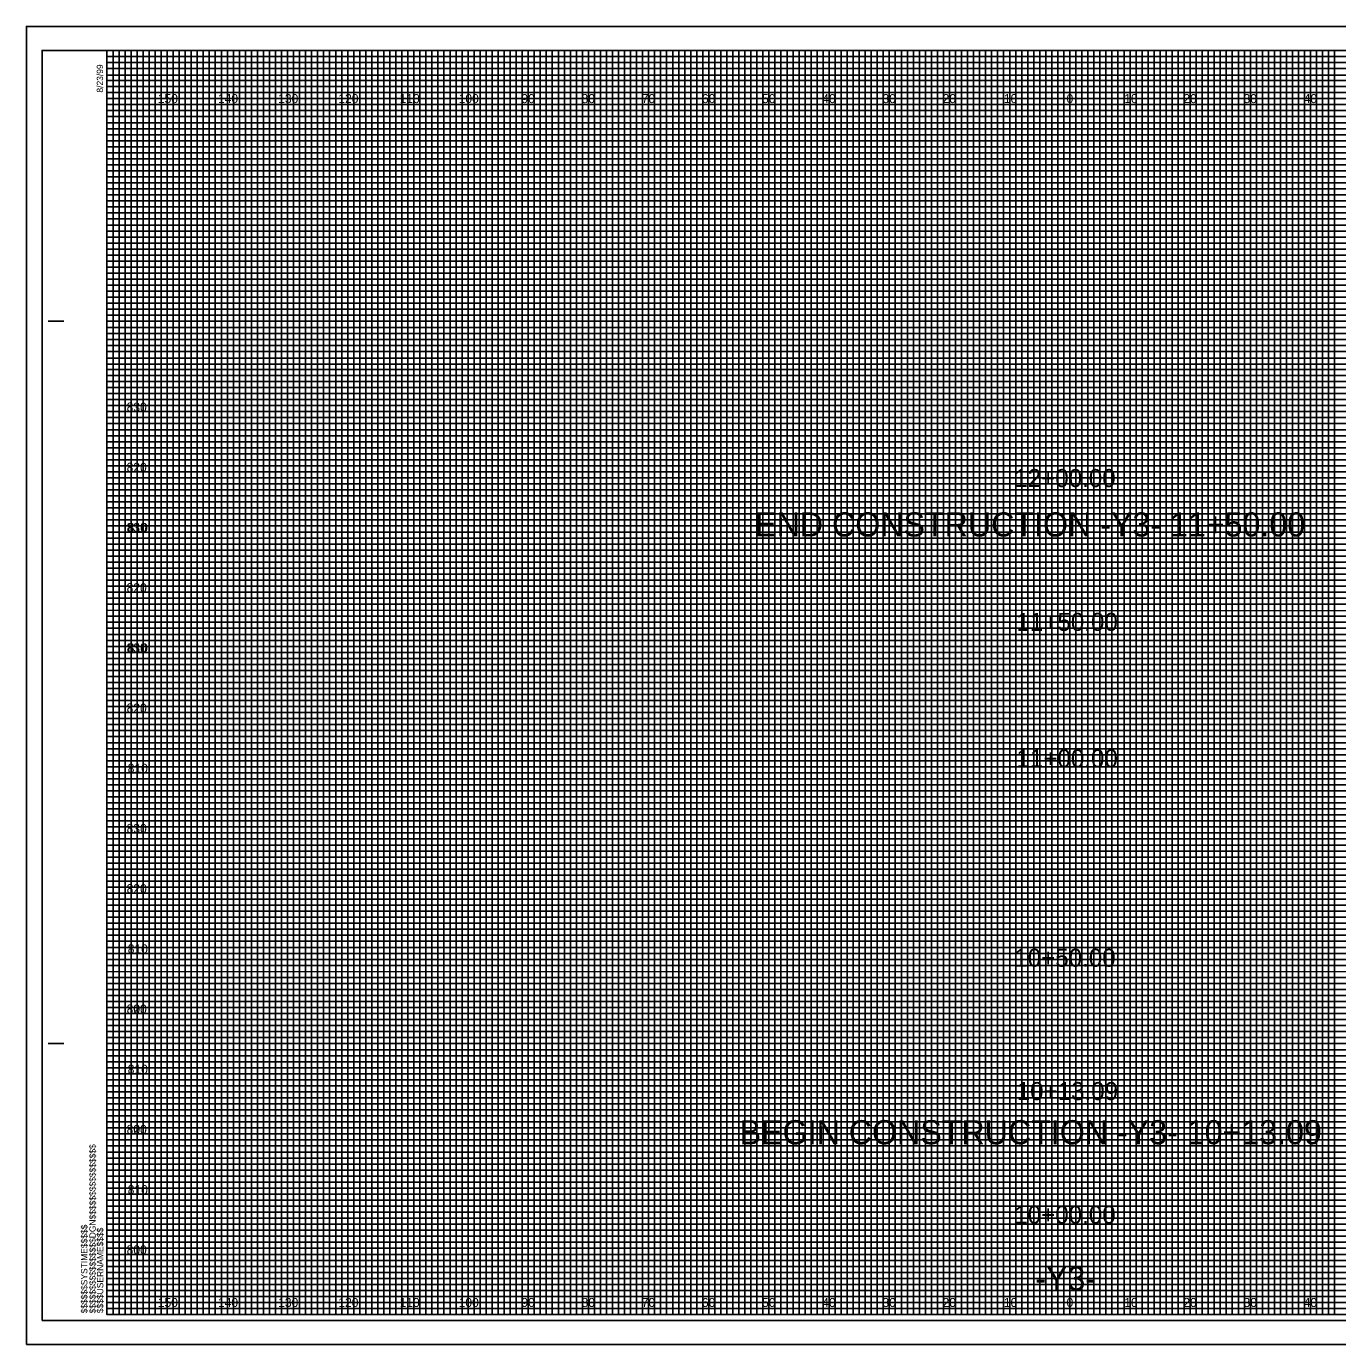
# Model space of a CAD drawing. Extents: x -13 to 323, y -5 to 214.
# Drawn here: x -13.4 to 204.5, y -5 to 214 of the extents above; entities that cross this region are included whole.
import ezdxf

# ---------------------------------------------------------------- set-up
doc = ezdxf.new("R2010")
doc.units = 0
for name, color, linetype in [('Prop XS Alignment Label', 7, 'Continuous'), ('Prop XS Elevation Labels', 7, 'Continuous'), ('Prop XS Offset Labels', 7, 'Continuous'), ('Prop XS Station Labels', 7, 'Continuous'), ('Sheet Cross Section CELL', 7, 'Continuous'), ('Sheet Cross Section Grid Major CELL', 7, 'Continuous'), ('Sheet Cross Section Grid Middle CELL', 7, 'Continuous'), ('Sheet Cross Section Grid Minor 1 CELL', 7, 'Continuous'), ('Sheet Cross Section Grid Minor 2 CELL', 7, 'Continuous'), ('Sheet Cutting Line CELL', 7, 'Continuous'), ('Sheet DOT Grid CELL', 7, 'Continuous'), ('Sheet Plot Border Inside CELL', 7, 'Continuous'), ('Sheet Plot Border Outside CELL', 7, 'Continuous')]:
    doc.layers.add(name, color=color, linetype=linetype)

msp = doc.modelspace()

# ---------------------------------------------------------------- linework, layer by layer
at = {"layer": 'Sheet Cross Section CELL'}
for p, q in [((-9.8, 165), (-7.3, 165)), ((-9.7, 165), (-7.2, 165)), ((-9.8, 45), (-7.3, 45)), ((-9.7, 45), (-7.2, 45)), ((0, 0), (0, 0)), ((0, 0), (0, 0)), ((0, 0), (0, 0)), ((0, 0), (0, 0)), ((0, 0), (0, 0)), ((0, 0), (0, 0)), ((0, 0), (0, 0))]:
    msp.add_line(p, q, dxfattribs=at)
msp.add_lwpolyline([(320, 210), (0, 210), (0, 0), (320, 0)], close=True, dxfattribs=at)
at = {"layer": 'Sheet Cross Section Grid Major CELL'}
for p, q in [((10, 210), (0, 210)), ((10, 0), (10, 210)), ((30, 210), (20, 210)), ((20, 210), (20, 0)), ((30, 0), (30, 210)), ((50, 210), (40, 210)), ((40, 210), (40, 0)), ((50, 0), (50, 210)), ((70, 210), (60, 210)), ((60, 210), (60, 0)), ((70, 0), (70, 210)), ((90, 210), (80, 210)), ((80, 210), (80, 0)), ((90, 0), (90, 210)), ((110, 210), (100, 210)), ((100, 210), (100, 0)), ((110, 0), (110, 210)), ((130, 210), (120, 210)), ((120, 210), (120, 0)), ((130, 0), (130, 210)), ((150, 210), (140, 210)), ((140, 210), (140, 0)), ((150, 0), (150, 210)), ((170, 210), (160, 210)), ((160, 210), (160, 0)), ((170, 0), (170, 210)), ((190, 210), (180, 210)), ((180, 210), (180, 0)), ((190, 0), (190, 210)), ((210, 210), (200, 210)), ((200, 210), (200, 0)), ((20, 0), (10, 0)), ((40, 0), (30, 0)), ((60, 0), (50, 0)), ((80, 0), (70, 0)), ((100, 0), (90, 0)), ((120, 0), (110, 0)), ((140, 0), (130, 0)), ((160, 0), (150, 0)), ((180, 0), (170, 0)), ((200, 0), (190, 0))]:
    msp.add_line(p, q, dxfattribs=at)
for points in [[(0, 200), (320, 200), (320, 190), (0, 190)], [(0, 180), (320, 180), (320, 170), (0, 170)], [(0, 160), (320, 160), (320, 150), (0, 150)], [(0, 140), (320, 140), (320, 130), (0, 130)], [(0, 120), (320, 120), (320, 110), (0, 110)], [(0, 100), (320, 100), (320, 90), (0, 90)], [(0, 80), (320, 80), (320, 70), (0, 70)], [(0, 60), (320, 60), (320, 50), (0, 50)], [(0, 40), (320, 40), (320, 30), (0, 30)], [(0, 20), (320, 20), (320, 10), (0, 10)]]:
    msp.add_lwpolyline(points, dxfattribs=at)
at = {"layer": 'Sheet Cross Section Grid Middle CELL'}
for points in [[(0, 210), (5, 210), (5, 0), (15, 0), (15, 210), (25, 210), (25, 0), (35, 0), (35, 210), (45, 210), (45, 0), (55, 0), (55, 210), (65, 210), (65, 0), (75, 0), (75, 210), (85, 210), (85, 0), (95, 0), (95, 210), (105, 210), (105, 0), (115, 0), (115, 210), (125, 210), (125, 0), (135, 0), (135, 210), (145, 210), (145, 0), (155, 0), (155, 210), (165, 210), (165, 0), (175, 0), (175, 210), (185, 210), (185, 0), (195, 0), (195, 210), (205, 210)], [(0, 205), (275, 205)], [(0, 185), (320, 185), (320, 195), (0, 195)], [(0, 165), (320, 165), (320, 175), (0, 175)], [(0, 145), (320, 145), (320, 155), (0, 155)], [(0, 125), (320, 125), (320, 135), (0, 135)], [(0, 105), (320, 105), (320, 115), (0, 115)], [(0, 85), (320, 85), (320, 95), (0, 95)], [(0, 65), (320, 65), (320, 75), (0, 75)], [(0, 45), (320, 45), (320, 55), (0, 55)], [(0, 25), (320, 25), (320, 35), (0, 35)], [(0, 5), (320, 5), (320, 15), (0, 15)]]:
    msp.add_lwpolyline(points, dxfattribs=at)
at = {"layer": 'Sheet Cross Section Grid Minor 1 CELL'}
for p, q in [((0, 209), (260, 209)), ((260, 207.98), (0, 207.98)), ((0, 207.98), (0, 207)), ((0, 207), (260, 207)), ((260, 205.89), (0, 205.89)), ((0, 205.89), (0, 204)), ((0, 204), (320, 204))]:
    msp.add_line(p, q, dxfattribs=at)
for points in [[(0, 203), (270, 203), (320, 203), (320, 202), (0, 202)], [(0, 201), (320, 201), (320, 199), (0, 199)], [(0, 198), (320, 198), (320, 197), (0, 196.98)], [(0, 196), (320, 196), (320, 194), (0, 194)], [(0, 193), (320, 193), (320, 192), (0, 192)], [(0, 191), (320, 191), (320, 189), (0, 189)], [(0, 188), (320, 188), (320, 187), (0, 187)], [(0, 186), (320, 186), (320, 184), (0, 184)], [(0, 183), (320, 183), (320, 182), (0, 182)], [(0, 181), (320, 181), (320, 179), (0, 179)], [(0, 178), (320, 178), (320, 177), (0, 177)], [(0, 176), (320, 176), (320, 173.95), (320, 173), (320, 172), (0, 172)], [(0, 174), (320, 174), (320, 173), (0, 173)], [(0, 171), (320, 171), (320, 169), (0, 169.03)], [(0, 169.03), (320, 169), (320, 168), (0, 168)], [(0, 167), (320, 167), (320, 166), (0, 166)], [(0, 164), (320, 164), (320, 163), (0, 163)], [(0, 162), (320, 162), (320, 161), (0, 161)], [(-0.07, 158.89), (320, 158.89), (320, 157.88), (-0.07, 157.88)], [(0, 157), (320, 157), (320, 156), (0, 156)], [(0, 154), (320, 154), (320, 153), (0, 153)], [(0, 152), (320, 152), (320, 151), (0, 151)], [(0, 149), (320, 149), (320, 148), (0, 148)], [(0, 147), (320, 147), (320, 146), (0, 146)], [(0, 144), (320, 144), (320, 143), (0, 143)], [(0, 142), (320, 142), (320, 141), (0, 141)], [(0, 139), (320, 139), (319.99, 137.98), (0, 138)], [(0, 137), (320, 137), (320, 136), (0, 136)], [(0, 134), (320, 134), (320, 133), (0, 133)], [(0, 132), (320, 132), (320, 131), (0, 131)], [(0, 129), (320, 129), (320, 128), (0, 128)], [(0, 127), (320, 127), (320, 126), (0, 126)], [(0, 124), (320, 124), (320, 123), (0, 123)], [(0, 122), (320, 122), (320, 121), (0, 121)], [(0, 119), (320, 119), (320, 118), (0, 118)], [(0, 116.99), (320.07, 116.91), (320, 116), (0, 116)], [(0, 114), (320, 114), (320, 113), (0, 113)], [(0, 112), (320, 112), (320, 111), (0, 111)], [(0, 109), (320, 109), (320, 108), (0, 108)], [(0, 107), (320, 107), (320, 106), (0, 106)], [(0, 104), (320, 104), (320, 103), (0, 103)], [(0, 102), (320, 102), (320, 101), (0, 101)], [(0, 99), (320, 99), (320, 98), (0, 98)], [(0, 97), (320, 97), (320, 96), (0, 96)], [(0, 94), (320, 94), (320, 93), (0, 93)], [(0, 92), (320, 92), (320, 91), (0, 91)], [(0, 89), (320, 89), (320, 88), (0, 88)], [(0, 87), (320, 87), (320, 86), (0, 86)], [(0, 84), (320, 84), (320, 83), (0, 83)], [(0, 82), (320, 82), (320, 81), (0, 81)], [(0, 79), (320, 79), (319.99, 77.98), (0, 78)], [(0, 77), (320, 77), (320, 76), (0, 76)], [(0, 74), (320, 74), (320, 73), (0, 73)], [(0, 72), (320, 72), (320, 71), (0, 71)], [(0, 69), (320, 69), (320, 68), (0, 68)], [(0, 67), (320, 67), (320, 66), (0, 66)], [(0, 64), (320, 64), (320, 63), (0, 63)], [(0, 62), (320, 62), (320, 61), (0, 61)], [(0, 59), (320, 59), (320, 58), (0, 58)], [(0, 56.99), (320.07, 56.91), (320, 56), (0, 56)], [(0, 54), (320, 54), (320, 53), (0, 53)], [(0, 52), (320, 52), (320, 51), (0, 51)], [(0, 49), (320, 49), (320, 48), (0, 48)], [(0, 47), (320, 47), (320, 46), (0, 46)], [(0, 44), (320, 44), (320, 43), (0, 43)], [(0, 42), (320, 42), (320, 41), (0, 41)], [(0, 39), (320, 39), (320, 38), (0, 38)], [(0, 37), (320, 37), (320, 36), (0, 36)], [(0, 34), (320, 34), (320, 33), (0, 33)], [(0, 32), (320, 32), (320, 31), (0, 31)], [(0, 29), (320, 29), (320, 28), (0, 28)], [(0, 27), (320, 27), (320, 26), (0, 26)], [(0, 24), (320, 24), (320, 23), (0, 23)], [(0, 22), (320, 22), (320, 21), (0, 21)], [(0, 19), (320, 19), (320, 18), (0, 18)], [(0, 17), (320, 17), (320, 16), (0, 16)], [(0, 14), (320, 14), (320, 13), (0, 13)], [(0, 12), (320, 12), (320, 11), (0, 11)], [(0, 9), (320, 9), (320, 8), (0, 8)], [(0, 7), (320, 7), (320, 6), (0, 6)], [(0, 4), (320, 4), (320, 3), (0, 3)], [(0, 2), (320, 2), (320, 1), (0, 1)]]:
    msp.add_lwpolyline(points, dxfattribs=at)
at = {"layer": 'Sheet Cross Section Grid Minor 2 CELL'}
for points in [[(0, 0), (1, 0), (1, 210), (2, 210), (2, 0)], [(2, 0), (3, 0), (3, 210), (4, 210), (4, 0)], [(5, 0), (6, 0), (6, 210), (7, 210), (7, 0)], [(7, 0), (8, 0), (8, 210), (9, 210), (9, 0)], [(10, 0), (11, 0), (11, 210), (12, 210), (12, 0)], [(12, 0), (13, 0), (13, 210), (14, 210), (14, 0)], [(15, 0), (16, 0), (16, 210), (17, 210), (17, 0)], [(17, 0), (18, 0), (18, 210), (19, 210), (19, 0)], [(20, 0), (21, 0), (21, 210), (22, 210), (22, 0)], [(22, 0), (23, 0), (23, 210), (24, 210), (24, 0)], [(25, 0), (26, 0), (26, 210), (27, 210), (27, 0)], [(27, 0), (28, 0), (28, 210), (29, 210), (29, 0)], [(30, 0), (31, 0), (31, 210), (32, 210), (32, 0)], [(32, 0), (33, 0), (33, 210), (34, 210), (34, 0)], [(35, 0), (36, 0), (36, 210), (37, 210), (37, 0)], [(37, 0), (38, 0), (38, 210), (39, 210), (39, 0)], [(40, 0), (41, 0), (41, 210), (42, 210), (42, 0)], [(42, 0), (43, 0), (43, 210), (44, 210), (44, 0)], [(45, 0), (46, 0), (46, 210), (47, 210), (47, 0)], [(47, 0), (48, 0), (48, 210), (49, 210), (49, 0)], [(50, 0), (51, 0), (51, 210), (52, 210), (52, 0)], [(52, 0), (53, 0), (53, 210), (54, 210), (54, 0)], [(55, 0), (56, 0), (56, 210), (57, 210), (57, 0)], [(57, 0), (58, 0), (58, 210), (59, 210), (59, 0)], [(60, 0), (61, 0), (61, 210), (62, 210), (62, 0)], [(62, 0), (63, 0), (63, 210), (64, 210), (64, 0)], [(65, 0), (66, 0), (66, 210), (67, 210), (67, 0)], [(67, 0), (68, 0), (68, 210), (69, 210), (69, 0)], [(70, 0), (71, 0), (71, 210), (72, 210), (72, 0)], [(72, 0), (73, 0), (73, 210), (74, 210), (74, 0)], [(75, 0), (76, 0), (76, 210), (77, 210), (77, 0)], [(77, 0), (78, 0), (78, 210), (79, 210), (79, 0)], [(80, 0), (81, 0), (81, 210), (82, 210), (82, 0)], [(82, 0), (83, 0), (83, 210), (84, 210), (84, 0)], [(85, 0), (86, 0), (86, 210), (87, 210), (87, 0)], [(87, 0), (88, 0), (88, 210), (89, 210), (89, 0)], [(90, 0), (91, 0), (91, 210), (92, 210), (92, 0)], [(92, 0), (93, 0), (93, 210), (94, 210), (94, 0)], [(95, 0), (96, 0), (96, 210), (97, 210), (97, 0)], [(97, 0), (98, 0), (98, 210), (99, 210), (99, 0)], [(100, 0), (101, 0), (101, 210), (102, 210), (102, 0)], [(102, 0), (103, 0), (103, 210), (104, 210), (104, 0)], [(105, 0), (106, 0), (106, 210), (107, 210), (107, 0)], [(107, 0), (108, 0), (108, 210), (109, 210), (109, 0)], [(110, 0), (111, 0), (111, 210), (112, 210), (112, 0)], [(112, 0), (113, 0), (113, 210), (114, 210), (114, 0)], [(115, 0), (116, 0), (116, 210), (117, 210), (117, 0)], [(117, 0), (118, 0), (118, 210), (119, 210), (119, 0)], [(120, 0), (121, 0), (121, 210), (122, 210), (122, 0)], [(122, 0), (123, 0), (123, 210), (124, 210), (124, 0)], [(125, 0), (126, 0), (126, 210), (127, 210), (127, 0)], [(127, 0), (128, 0), (128, 210), (129, 210), (129, 0)], [(130, 0), (131, 0), (131, 210), (132, 210), (132, 0)], [(132, 0), (133, 0), (133, 210), (134, 210), (134, 0)], [(135, 0), (136, 0), (136, 210), (137, 210), (137, 0)], [(137, 0), (138, 0), (138, 210), (139, 210), (139, 0)], [(140, 0), (141, 0), (141, 210), (142, 210), (142, 0)], [(142, 0), (143, 0), (143, 210), (144, 210), (144, 0)], [(145, 0), (146, 0), (146, 210), (147, 210), (147, 0)], [(147, 0), (148, 0), (148, 210), (149, 210), (149, 0)], [(150, 0), (151, 0), (151, 210), (152, 210), (152, 0)], [(152, 0), (153, 0), (153, 210), (154, 210), (154, 0)], [(155, 0), (156, 0), (156, 210), (157, 210), (157, 0)], [(157, 0), (158, 0), (158, 210), (159, 210), (159, 0)], [(160, 0), (161, 0), (161, 210), (162, 210), (162, 0)], [(162, 0), (163, 0), (163, 210), (164, 210), (164, 0)], [(165, 0), (166, 0), (166, 210), (167, 210), (167, 0)], [(167, 0), (168, 0), (168, 210), (169, 210), (169, 0)], [(170, 0), (171, 0), (171, 210), (172, 210), (172, 0)], [(172, 0), (173, 0), (173, 210), (174, 210), (174, 0)], [(175, 0), (176, 0), (176, 210), (177, 210), (177, 0)], [(177, 0), (178, 0), (178, 210), (179, 210), (179, 0)], [(180, 0), (181, 0), (181, 210), (182, 210), (182, 0)], [(182, 0), (183, 0), (183, 210), (184, 210), (184, 0)], [(185, 0), (186, 0), (186, 210), (187, 210), (187, 0)], [(187, 0), (188, 0), (188, 210), (189, 210), (189, 0)], [(190, 0), (191, 0), (191, 210), (192, 210), (192, 0)], [(192, 0), (193, 0), (193, 210), (194, 210), (194, 0)], [(195, 0), (196, 0), (196, 210), (197, 210), (197, 0)], [(197, 0), (198, 0), (198, 210), (199, 210), (199, 0)], [(200, 0), (201, 0), (201, 210), (202, 210), (202, 0)], [(202, 0), (203, 0), (203, 210), (204, 210), (204, 0)]]:
    msp.add_lwpolyline(points, dxfattribs=at)
at = {"layer": 'Sheet Cutting Line CELL'}
for p, q in [((323.3, 214), (-13.4, 214)), ((-13.4, 214), (-13.4, -5)), ((-13.4, -5), (323.3, -5))]:
    msp.add_line(p, q, dxfattribs=at)
at = {"layer": 'Sheet DOT Grid CELL'}
for p, q in [((10, 0), (10, 210)), ((20, 0), (20, 210)), ((30, 0), (30, 210)), ((40, 0), (40, 210)), ((50, 0), (50, 210)), ((60, 0), (60, 210)), ((70, 0), (70, 210)), ((80, 0), (80, 210)), ((90, 0), (90, 210)), ((100, 0), (100, 210)), ((110, 0), (110, 210)), ((120, 0), (120, 210)), ((130, 0), (130, 210)), ((140, 0), (140, 210)), ((150, 0), (150, 210)), ((160, 0), (160, 210)), ((170, 0), (170, 210)), ((180, 0), (180, 210)), ((190, 0), (190, 210)), ((200, 0), (200, 210)), ((0, 200), (320, 200)), ((0, 190), (320, 190)), ((0, 180), (320, 180)), ((0, 170), (320, 170)), ((0, 160), (320, 160)), ((0, 150), (320, 150)), ((0, 140), (320, 140)), ((0, 130), (320, 130)), ((0, 120), (320, 120)), ((0, 110), (320, 110)), ((0, 100), (320, 100)), ((0, 90), (320, 90)), ((0, 80), (320, 80)), ((0, 70), (320, 70)), ((0, 60), (320, 60)), ((0, 50), (320, 50)), ((0, 40), (320, 40)), ((0, 30), (320, 30)), ((0, 20), (320, 20)), ((0, 10), (320, 10))]:
    msp.add_line(p, q, dxfattribs=at)
at = {"layer": 'Sheet Plot Border Inside CELL'}
msp.add_lwpolyline([(-10.8, -1), (322.4, -1), (322.4, 210), (-10.8, 210)], close=True, dxfattribs=at)
at = {"layer": 'Sheet Plot Border Outside CELL'}
msp.add_lwpolyline([(-13.4, -5), (323.3, -5), (323.3, 214), (-13.4, 214)], close=True, dxfattribs=at)

# ---------------------------------------------------------------- texts
at = {"layer": 'Prop XS Alignment Label'}
for s, p in [('END CONSTRUCTION -Y3- 11+50.00', (107.7, 129.26)), ('BEGIN CONSTRUCTION -Y3- 10+13.09', (105.13, 28.29)), ('-Y3-', (154.25, 4))]:
    msp.add_text(s, height=4, dxfattribs=at).set_placement(p)
at = {"layer": 'Prop XS Elevation Labels'}
for s, p in [('830', (3.26, 150)), ('820', (3.26, 140)), ('830', (3.26, 130)), ('810', (3.44, 130)), ('820', (3.26, 120)), ('830', (3.26, 110)), ('810', (3.44, 110)), ('820', (3.26, 100)), ('810', (3.44, 90)), ('830', (3.26, 80)), ('820', (3.26, 70)), ('810', (3.44, 60)), ('820', (3.26, 50)), ('800', (3.26, 50)), ('810', (3.44, 40)), ('820', (3.26, 30)), ('800', (3.26, 30)), ('810', (3.44, 20)), ('800', (3.26, 10))]:
    msp.add_text(s, height=1.5, dxfattribs=at).set_placement(p)
at = {"layer": 'Prop XS Offset Labels'}
for s, p in [('150', (8.44, 201.25)), ('140', (18.44, 201.25)), ('130', (28.44, 201.25)), ('120', (38.44, 201.25)), ('110', (48.62, 201.25)), ('100', (58.44, 201.25)), ('90', (68.86, 201.25)), ('80', (78.86, 201.25)), ('70', (88.86, 201.25)), ('60', (98.86, 201.25)), ('50', (108.86, 201.25)), ('40', (118.86, 201.25)), ('30', (128.86, 201.25)), ('20', (138.86, 201.25)), ('10', (149.04, 201.25)), ('0', (159.45, 201.25)), ('0', (159.45, 201.25)), ('10', (169.04, 201.25)), ('20', (178.86, 201.25)), ('30', (188.86, 201.25)), ('40', (198.86, 201.25)), ('150', (8.44, 1.25)), ('140', (18.44, 1.25)), ('130', (28.44, 1.25)), ('120', (38.44, 1.25)), ('110', (48.62, 1.25)), ('100', (58.44, 1.25)), ('90', (68.86, 1.25)), ('80', (78.86, 1.25)), ('70', (88.86, 1.25)), ('60', (98.86, 1.25)), ('50', (108.86, 1.25)), ('40', (118.86, 1.25)), ('30', (128.86, 1.25)), ('20', (138.86, 1.25)), ('10', (149.04, 1.25)), ('0', (159.45, 1.25)), ('0', (159.45, 1.25)), ('10', (169.04, 1.25)), ('20', (178.86, 1.25)), ('30', (188.86, 1.25)), ('40', (198.86, 1.25))]:
    msp.add_text(s, height=1.5, dxfattribs=at).set_placement(p)
at = {"layer": 'Prop XS Station Labels'}
for s, p in [('12+00.00', (150.77, 137.46)), ('11+50.00', (151.13, 113.57)), ('11+00.00', (151.13, 90.89)), ('10+50.00', (150.77, 57.78)), ('10+13.09', (151.17, 35.62)), ('10+00.00', (150.77, 15.1))]:
    msp.add_text(s, height=3, dxfattribs=at).set_placement(p)
at = {"layer": 'Sheet Cross Section CELL'}
for s, p in [('8/23/99', (-0.65, 203)), ('$$$$$$$$$$$$$$$$DGN$$$$$$$$$$$$$$$$', (-1.88, 0.18)), ('$$$$$$SYSTIME$$$$$', (-3.26, 0.18)), ('$$$$USERNAME$$$$', (-0.62, 0.23))]:
    msp.add_text(s, height=1.05, rotation=90, dxfattribs=at).set_placement(p)

doc.saveas('drawing.dxf')
